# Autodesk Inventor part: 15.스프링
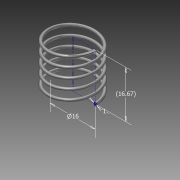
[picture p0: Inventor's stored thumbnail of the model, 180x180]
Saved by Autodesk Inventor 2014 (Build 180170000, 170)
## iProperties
Created: 2015-11
Part Number: 15.스프링
Material: 강철, 탄소
Document SubType Name: Modeling
Designer: SEC
Mass: 1.5393 g
Surface Area: 7.90158 cm^2
Volume: 0.195591 cm^3
Density: 7.87 g/cm^3
Appearance: 반연마
Author: SEC
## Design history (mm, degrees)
sketch "스케치1"
  geometry: L1 (0, 0)-(8, 0); L2 (8, 0)-(8, 16.67); L3 (8, 16.67)-(0, 16.67); L4 (0, 16.67)-(0, 0); C1 r 0.5 at (8, 0)
  constraints: 8 end point, 2 parallel, 1 centre point, 1 coincident, 1 horizontal, 1 perpendicular
  dimensions: "d1" = 16 diameter of L2 L4; "d2" = 16.66987 distance of L1.end L2.end (derived); "d3" = 1 diameter of C1
feature "코일1" pitch "d4" = 10; turns "d6" = 5; dims "d5" = 16.66987 (= d2), "d7" = 0, angle "d8" = 90 deg, angle "d9" = 90 deg, "d10" = 0, "d11" = 0
sketch "스케치2"
  geometry: L1 (-8.5, 0)-(-7.5, 0) reference; 1 further point
  constraints: 1 horizontal alignment
extrude "돌출1" cut sketch "스케치2" stored distance "d12" = 10; taper "d13" = 0 deg
node "작업 평면2"
sketch "스케치3"
  geometry: L1 (0.5, 0)-(-0.5, 0) reference; 1 further point
  constraints: 1 horizontal alignment
extrude "돌출2" cut sketch "스케치3" stored distance "d15" = 10; taper "d16" = 0 deg
node "솔리드1"
node "절단 모서리 투영1"
node "절단 모서리 투영2"
other parameters: "d14" = 0
